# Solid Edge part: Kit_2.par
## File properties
Sűrűség: 0,000 kg/m^3
Pontosság: 0,990
Author: bmolnar
Last saved by: bmolnar
Revision: 76
Username: bmolnar
Dokumentum tartalom típus: 0
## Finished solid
Body 1: solid body, 21 faces, 37 edges, 27 vertices.
  Faces by surface: cylinder 10, plane 9, cone 1, torus 1
  Edges by curve: circle 23, line 14
Bounding box of the edges (mm; curved faces can reach further): 68.000 x 67.800 x 6.000, from (-34, -32.35, 0.65) to (34, 35.45, 6.65).
Cylindrical faces by radius (mm): R1.5 x2, R3 x4, R23.5 x1, R29.65 x1, R32.35 x1, R34 x1
Conical faces (half-angle, radius in mm at the cone's reference point): 45 deg R23 x1
Toroidal faces (ring radius, tube radius in mm): R24.3 r0.8 x1
Planar faces by outward normal: +z 2, -z 5, oblique 2
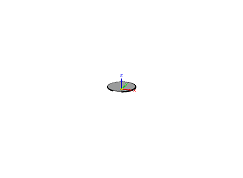
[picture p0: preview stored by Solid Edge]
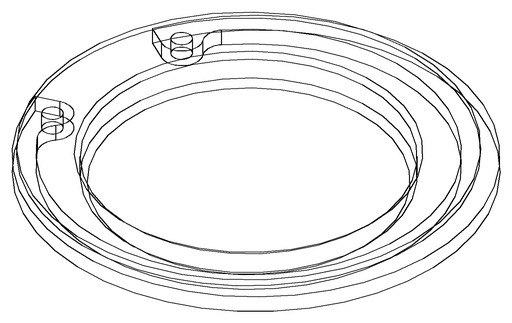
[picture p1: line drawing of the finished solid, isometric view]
